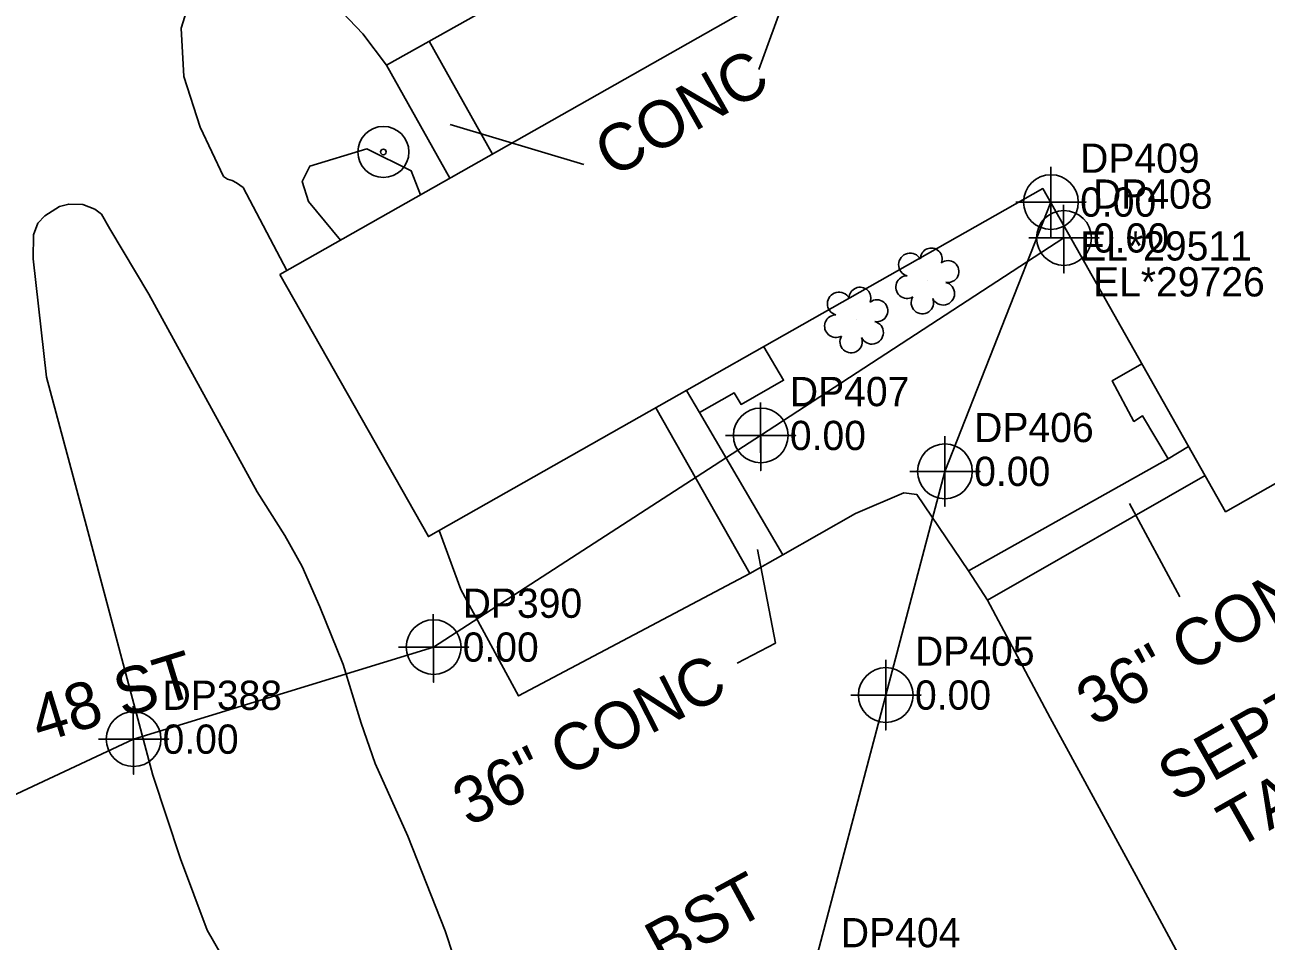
# Model space of a CAD drawing. Extents: x 1182322 to 1186765, y 572295 to 575411.
# Drawn here: x 1184140.3 to 1184246.4, y 573165.3 to 573243.6 of the extents above; entities that cross this region are included whole.
import ezdxf

# ---------------------------------------------------------------- set-up
doc = ezdxf.new("R2010")
doc.units = 0
for name, color, linetype in [('Exist Building', 7, 'Continuous'), ('Exist Other Culture Area Outline', 7, 'Continuous'), ('Exist Other Culture Area Outline Leader', 7, 'Continuous'), ('Exist Other Culture Area Outline Text', 7, 'Continuous'), ('Exist Right of Way Line', 7, 'Continuous'), ('Exist Roads EOP Other', 7, 'Continuous'), ('Exist Roads EOP Other Text', 7, 'Continuous'), ('Exist Utilities Other Located Object CELL', 7, 'Continuous'), ('Exist Utilities Power UG Cable SUE LOS B', 7, 'Continuous'), ('Exist Utilities Power UG Cable SUE LOS B Cogo Comment', 7, 'Continuous'), ('Exist Utilities Power UG Cable SUE LOS B Cogo Elevation', 7, 'Continuous'), ('Exist Utilities Power UG Cable SUE LOS B Cogo Number', 7, 'Continuous'), ('Exist Utilities Power UG Cable SUE LOS B Cogo Point CELL', 7, 'Continuous'), ('Exist Utilities Telephone UG Conduit SUE LOS B', 7, 'Continuous'), ('Exist Utilities Telephone UG Conduit SUE LOS B Cogo Comment', 7, 'Continuous'), ('Exist Utilities Telephone UG Conduit SUE LOS B Cogo Elevation', 7, 'Continuous'), ('Exist Utilities Telephone UG Conduit SUE LOS B Cogo Number', 7, 'Continuous'), ('Exist Utilities Telephone UG Conduit SUE LOS B Cogo Point CELL', 7, 'Continuous'), ('Exist Utilities Telephone UG Conduit SUE LOS B Text', 7, 'Continuous'), ('Exist Vegetation Hedge Row', 7, 'Continuous'), ('Exist Vegetation Shrub CELL', 7, 'Continuous')]:
    doc.layers.add(name, color=color, linetype=linetype)

msp = doc.modelspace()

# ---------------------------------------------------------------- linework, layer by layer
at = {"layer": 'Exist Building'}
msp.add_lwpolyline([(1184162.11, 573222.26), (1184270.65, 573283.73), (1184298.98, 573233.71), (1184242.97, 573201.99), (1184227.33, 573229.61), (1184174.8, 573199.86)], close=True, dxfattribs=at)
at = {"layer": 'Exist Other Culture Area Outline'}
for p, q in [((1184194.24, 573210.87), (1184202.28, 573196.7)), ((1184241.22, 573205.08), (1184222.6, 573194.44))]:
    msp.add_line(p, q, dxfattribs=at)
for points in [[(1184180.27, 573232.55), (1184174.86, 573242.21)], [(1184176.63, 573230.49), (1184171.22, 573240.17)], [(1184197.97, 573210.46), (1184200.95, 573212.15), (1184201.54, 573211.16), (1184205.17, 573213.23), (1184203.47, 573216.09)], [(1184235.81, 573214.63), (1184233.26, 573213.17), (1184235.13, 573209.71), (1184235.85, 573210.19), (1184238.05, 573206.5)], [(1184205.1, 573198.3), (1184197.97, 573210.46), (1184196.86, 573212.35)], [(1184220.99, 573196.93), (1184238.05, 573206.5), (1184239.81, 573207.56)]]:
    msp.add_lwpolyline(points, dxfattribs=at)
at = {"layer": 'Exist Other Culture Area Outline Leader'}
for p, q in [((1184207.72, 573252.67), (1184203.07, 573239.79)), ((1184176.67, 573235.1), (1184188.08, 573231.68)), ((1184234.74, 573202.7), (1184239.07, 573194.72))]:
    msp.add_line(p, q, dxfattribs=at)
msp.add_lwpolyline([(1184202.95, 573198.77), (1184204.49, 573190.76), (1184201.19, 573189.05)], dxfattribs=at)
at = {"layer": 'Exist Right of Way Line'}
msp.add_arc((1124762.27, 616900.03), 73589.16, 323.6095929, 324.0203142, dxfattribs=at)
at = {"layer": 'Exist Roads EOP Other'}
for points in [[(1184165.13, 573247.13), (1184169.18, 573242.84), (1184171.22, 573240.17), (1184212.6, 573263.32)], [(1184162.7, 573222.6), (1184158.95, 573229.69), (1184158.4, 573230.09), (1184158.03, 573230.31), (1184157.61, 573230.42), (1184157.29, 573230.65), (1184155.28, 573234.85), (1184153.9, 573239.18), (1184153.65, 573243.32), (1184154.26, 573245.24)], [(1184155.87, 573166.22), (1184153.6, 573172.33), (1184151.25, 573179.46), (1184145.57, 573200.76), (1184142.13, 573213.5), (1184141.01, 573223.61), (1184141.02, 573225.66), (1184141.4, 573226.66), (1184141.99, 573227.27), (1184143.25, 573228.07), (1184144.04, 573228.29), (1184145.24, 573228.25), (1184146.28, 573227.86), (1184146.84, 573227.41), (1184147.55, 573226.17), (1184150.9, 573220.59), (1184160.15, 573203.7), (1184162.52, 573199.96), (1184164.01, 573197.31), (1184165.53, 573193.87), (1184167.51, 573188.94), (1184169.04, 573183.91)], [(1184243.27, 573156.11), (1184235.31, 573170.87), (1184227.98, 573184.38), (1184222.6, 573194.44), (1184220.99, 573196.93), (1184216.57, 573203.46), (1184215.46, 573203.6), (1184211.33, 573201.84), (1184205.1, 573198.3), (1184202.28, 573196.7), (1184182.51, 573186.25), (1184177.56, 573195.35)], [(1184177.56, 573195.35), (1184175.73, 573200.39)], [(1184155.87, 573166.22), (1184157.08, 573164.15), (1184159.04, 573161.27), (1184160.94, 573159.19), (1184162.65, 573157.63), (1184164.35, 573156.56), (1184166.06, 573156.03), (1184167.73, 573155.99), (1184169.73, 573156.44), (1184171.81, 573157.05), (1184174.44, 573158.52), (1184176.12, 573160.2), (1184176.92, 573161.63), (1184177.2, 573162.66), (1184176.96, 573164), (1184176.23, 573166.17), (1184173.03, 573174.26), (1184170.24, 573180.47), (1184169.04, 573183.91)]]:
    msp.add_lwpolyline(points, dxfattribs=at)
at = {"layer": 'Exist Utilities Other Located Object CELL'}
for radius in [2.18, 0.24]:
    msp.add_circle((1184170.95, 573232.74), radius, dxfattribs=at)
at = {"layer": 'Exist Utilities Power UG Cable SUE LOS B'}
msp.add_lwpolyline([(1184206.24, 573098.09), (1184205.84, 573128.77), (1184207.57, 573162.26), (1184213.91, 573186.32), (1184218.97, 573205.44), (1184228.03, 573228.46)], dxfattribs=at)
at = {"layer": 'Exist Utilities Power UG Cable SUE LOS B Cogo Point CELL'}
for points in [[(1184228.03, 573231.46), (1184228.03, 573225.46), (1184228.03, 573228.46), (1184231.03, 573228.46), (1184225.03, 573228.46)], [(1184218.97, 573208.44), (1184218.97, 573202.44), (1184218.97, 573205.44), (1184221.97, 573205.44), (1184215.97, 573205.44)], [(1184213.91, 573189.32), (1184213.91, 573183.32), (1184213.91, 573186.32), (1184216.91, 573186.32), (1184210.91, 573186.32)]]:
    msp.add_lwpolyline(points, dxfattribs=at)
for centre in [(1184228.03, 573228.46), (1184218.97, 573205.44), (1184213.91, 573186.32)]:
    msp.add_circle(centre, 2.34, dxfattribs=at)
at = {"layer": 'Exist Utilities Telephone UG Conduit SUE LOS B'}
msp.add_lwpolyline([(1184023.09, 573304.47), (1184046.48, 573279.29), (1184068.5, 573248.18), (1184095.84, 573211.96), (1184125, 573174.35), (1184127.35, 573172.14), (1184149.57, 573182.55), (1184175.23, 573190.42), (1184203.21, 573208.51), (1184229.13, 573225.39)], dxfattribs=at)
at = {"layer": 'Exist Utilities Telephone UG Conduit SUE LOS B Cogo Point CELL'}
for points in [[(1184229.11, 573228.21), (1184229.15, 573222.39), (1184229.13, 573225.39), (1184232.15, 573225.39), (1184226.15, 573225.39)], [(1184203.19, 573211.33), (1184203.22, 573205.51), (1184203.21, 573208.51), (1184206.22, 573208.51), (1184200.22, 573208.51)], [(1184175.22, 573193.23), (1184175.25, 573187.42), (1184175.23, 573190.42), (1184178.25, 573190.42), (1184172.25, 573190.42)], [(1184149.55, 573185.36), (1184149.59, 573179.55), (1184149.57, 573182.55), (1184152.59, 573182.55), (1184146.59, 573182.55)]]:
    msp.add_lwpolyline(points, dxfattribs=at)
for centre in [(1184229.15, 573225.39), (1184203.22, 573208.51), (1184175.25, 573190.42), (1184149.59, 573182.55)]:
    msp.add_circle(centre, 2.34, dxfattribs=at)
at = {"layer": 'Exist Vegetation Hedge Row'}
msp.add_lwpolyline([(1184167.28, 573225.19), (1184164.55, 573228.52), (1184164.01, 573230.23), (1184164.66, 573231.53), (1184169.54, 573233), (1184173.34, 573231.13), (1184174.13, 573229.07)], dxfattribs=at)
at = {"layer": 'Exist Vegetation Shrub CELL'}
for p, q in [((1184217.52, 573221.73), (1184217.52, 573221.73)), ((1184211.43, 573218.39), (1184211.43, 573218.39))]:
    msp.add_line(p, q, dxfattribs=at)
for centre, radius, start, end in [((1184216, 573223.11), 0.99, 28.9927, 254.6254), ((1184217.8, 573223.6), 0.929, 338.6103, 180.2398), ((1184219.23, 573222.52), 0.937, 259.145, 127.6137), ((1184215.74, 573221.19), 0.968, 90.0444, 299.5753), ((1184209.91, 573219.77), 0.99, 28.9927, 254.6254), ((1184211.71, 573220.25), 0.929, 338.6103, 180.2398), ((1184218.81, 573220.64), 0.984, 205.4333, 75.5406), ((1184213.15, 573219.17), 0.937, 259.145, 127.6137), ((1184217.04, 573219.86), 0.955, 149.2636, 22.107), ((1184209.65, 573217.85), 0.968, 90.0444, 299.5753), ((1184212.72, 573217.3), 0.984, 205.4333, 75.5406), ((1184210.95, 573216.52), 0.955, 149.2636, 22.107)]:
    msp.add_arc(centre, radius, start, end, dxfattribs=at)

# ---------------------------------------------------------------- texts
at = {"layer": 'Exist Other Culture Area Outline Text'}
for s, rotation, p in [('CONC', 29.5221, (1184190.54, 573230.48)), ('36" CONC', 29.7464, (1184231.75, 573183.56)), ('36" CONC', 27.057, (1184178.26, 573175.02)), ('SEPTIC', 29.5221, (1184238.71, 573177.07)), ('TANK', 29.5221, (1184243.83, 573173.08))]:
    msp.add_text(s, height=4, rotation=rotation, dxfattribs=at).set_placement(p)
at = {"layer": 'Exist Roads EOP Other Text'}
msp.add_text('BST', height=4, rotation=28.4785, dxfattribs=at).set_placement((1184194.81, 573162.88))
at = {"layer": 'Exist Utilities Power UG Cable SUE LOS B Cogo Comment'}
msp.add_text('EL*29511', height=2.5, dxfattribs=at).set_placement((1184230.53, 573223.46))
at = {"layer": 'Exist Utilities Power UG Cable SUE LOS B Cogo Elevation'}
for p in [(1184230.53, 573227.21), (1184221.47, 573204.19), (1184216.41, 573185.07)]:
    msp.add_text('0.00', height=2.5, dxfattribs=at).set_placement(p)
at = {"layer": 'Exist Utilities Power UG Cable SUE LOS B Cogo Number'}
for s, p in [('DP409', (1184230.53, 573230.96)), ('DP406', (1184221.47, 573207.94)), ('DP405', (1184216.41, 573188.82)), ('DP404', (1184210.07, 573164.76))]:
    msp.add_text(s, height=2.5, dxfattribs=at).set_placement(p)
at = {"layer": 'Exist Utilities Telephone UG Conduit SUE LOS B Cogo Comment'}
msp.add_text('EL*29726', height=2.5, dxfattribs=at).set_placement((1184231.63, 573220.39))
at = {"layer": 'Exist Utilities Telephone UG Conduit SUE LOS B Cogo Elevation'}
for p in [(1184231.63, 573224.14), (1184205.71, 573207.26), (1184177.73, 573189.17), (1184152.07, 573181.3)]:
    msp.add_text('0.00', height=2.5, dxfattribs=at).set_placement(p)
at = {"layer": 'Exist Utilities Telephone UG Conduit SUE LOS B Cogo Number'}
for s, p in [('DP408', (1184231.63, 573227.89)), ('DP407', (1184205.71, 573211.01)), ('DP390', (1184177.73, 573192.92)), ('DP388', (1184152.07, 573185.05))]:
    msp.add_text(s, height=2.5, dxfattribs=at).set_placement(p)
at = {"layer": 'Exist Utilities Telephone UG Conduit SUE LOS B Text'}
msp.add_text('48 ST', height=4, rotation=17.0396, dxfattribs=at).set_placement((1184141.55, 573182.19))

doc.saveas('drawing.dxf')
